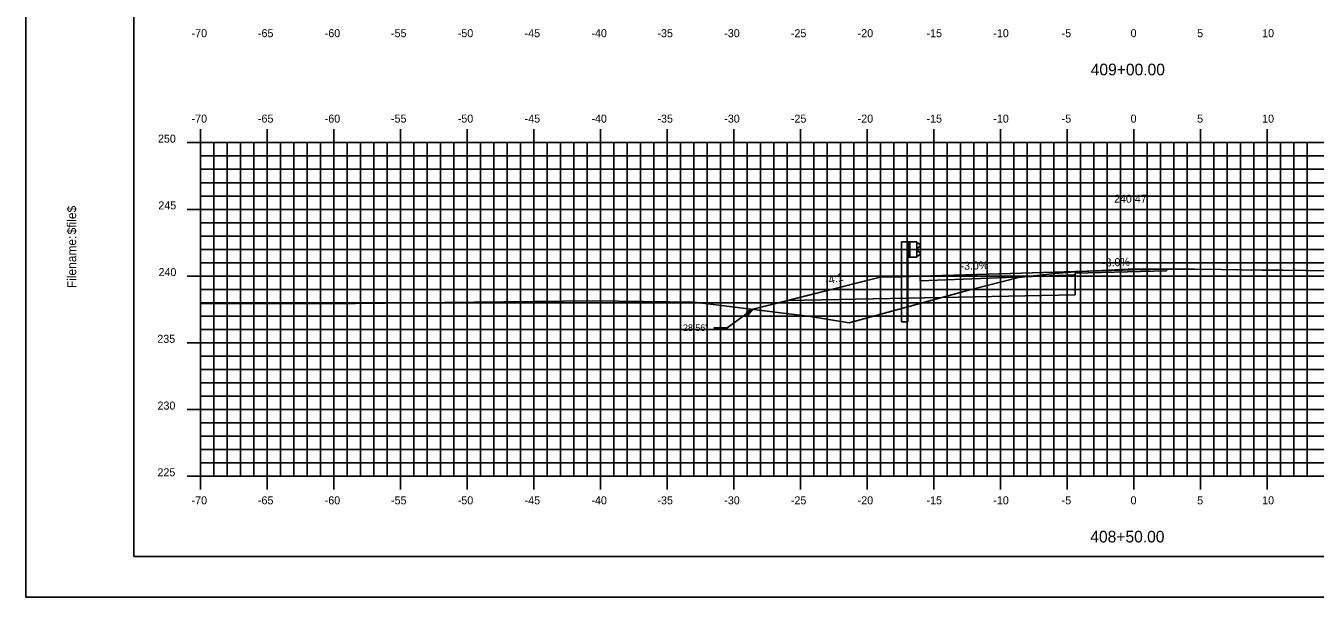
# Model space of a CAD drawing. Extents: x 1160718 to 1173142, y 616002 to 617630.
# Drawn here: x 1167440 to 1167536.7, y 616613.9 to 616656.7 of the extents above; entities that cross this region are included whole.
import ezdxf

# ---------------------------------------------------------------- set-up
doc = ezdxf.new("R2010")
doc.units = 0
for name, color, linetype in [('ANNOTATION', 7, 'Continuous'), ('BORDER', 7, 'Continuous'), ('D_Guardrail_Beam_Lt', 7, 'Continuous'), ('D_Roadway_Centerline', 7, 'Continuous'), ('D_Roadway_Centerline_Text', 7, 'Continuous'), ('D_Roadway_Edge_Shoulder', 7, 'Continuous'), ('D_Roadway_Edge_TW', 7, 'Continuous'), ('D_Roadway_Pavement', 7, 'Continuous'), ('D_Roadway_SubGrade', 7, 'Continuous'), ('H_V ANNOTATION', 7, 'Continuous'), ('MAJOR', 7, 'Continuous'), ('MINOR', 7, 'Continuous'), ('PLOT BOUNDARY', 7, 'Continuous'), ('S_Roadway_Centerline', 7, 'Continuous')]:
    doc.layers.add(name, color=color, linetype=linetype)

msp = doc.modelspace()

# ---------------------------------------------------------------- linework, layer by layer
at = {"layer": 'ANNOTATION'}
for p in [(1167494.509, 616635.442), (1167491.573, 616634.061)]:
    msp.add_line(p, (1167492.573, 616634.061), dxfattribs=at)
msp.add_lwpolyline([(1167518.683, 616636.522), (1167508.683, 616636.322), (1167497.072, 616636.089)], dxfattribs=at)
msp.add_lwpolyline([(1167494.029, 616635.253), (1167494.509, 616635.442), (1167494.174, 616635.05)], close=True, dxfattribs=at)
at = {"layer": 'BORDER'}
for p, q in [((1167448.072, 616721.928), (1167448.072, 616616.928)), ((1167448.072, 616616.928), (1167608.072, 616616.928))]:
    msp.add_line(p, q, dxfattribs=at)
at = {"layer": 'D_Guardrail_Beam_Lt'}
for p, q in [((1167505.642, 616640.505), (1167505.642, 616634.505)), ((1167506.113, 616640.505), (1167505.642, 616640.505)), ((1167506.801, 616640.505), (1167506.113, 616640.505)), ((1167506.113, 616640.505), (1167506.113, 616639.338)), ((1167506.176, 616640.505), (1167506.176, 616639.338)), ((1167506.28, 616640.505), (1167506.28, 616639.338)), ((1167506.801, 616639.338), (1167506.801, 616640.505)), ((1167506.801, 616640.422), (1167506.875, 616640.407)), ((1167506.891, 616640.4), (1167507.034, 616640.3)), ((1167506.875, 616639.436), (1167506.801, 616639.422)), ((1167506.805, 616639.957), (1167506.805, 616639.887)), ((1167507.034, 616640.157), (1167506.839, 616640.021)), ((1167506.839, 616639.822), (1167507.034, 616639.686)), ((1167507.034, 616639.543), (1167506.891, 616639.443)), ((1167506.113, 616639.338), (1167506.801, 616639.338)), ((1167506.134, 616634.505), (1167506.134, 616639.338)), ((1167506.134, 616634.505), (1167505.642, 616634.505))]:
    msp.add_line(p, q, dxfattribs=at)
for centre, major_axis, start_param, end_param in [((1167506.867, 616640.366), (0.0417, 0), 0.959931, 1.376053), ((1167506.884, 616639.957), (-0.0789, 0), 5.323254, 6.283185), ((1167506.884, 616639.887), (-0.0789, 0), 6.283185, 7.243116), ((1167506.867, 616639.477), (0.0417, 0), 4.907132, 5.323254), ((1167506.984, 616640.229), (0.0877, 0), 5.323254, 7.243116), ((1167506.984, 616639.615), (0.0877, 0), 5.323254, 7.243116)]:
    msp.add_ellipse(centre, major_axis=major_axis, ratio=0.995501, start_param=start_param, end_param=end_param, dxfattribs=at)
at = {"layer": 'D_Roadway_Centerline'}
msp.add_lwpolyline([(1167494.509, 616635.442), (1167496.76, 616636.004), (1167496.76, 616636.004), (1167504.063, 616637.856), (1167505.578, 616637.879), (1167507.063, 616637.916), (1167513.059, 616638.095), (1167518.683, 616638.265), (1167523.072, 616638.397), (1167525.526, 616638.454)], dxfattribs=at)
at = {"layer": 'D_Roadway_Edge_Shoulder'}
msp.add_lwpolyline([(1167507.063, 616637.916), (1167507.063, 616637.583)], dxfattribs=at)
at = {"layer": 'D_Roadway_Edge_TW'}
msp.add_line((1167525.526, 616638.454), (1167525.526, 616638.329), dxfattribs=at)
msp.add_lwpolyline([(1167525.526, 616638.329), (1167525.526, 616638.454), (1167523.072, 616638.397), (1167507.063, 616637.916), (1167507.063, 616637.583), (1167518.683, 616638.023), (1167518.683, 616638.14)], close=True, dxfattribs=at)
at = {"layer": 'D_Roadway_Pavement'}
msp.add_lwpolyline([(1167507.063, 616637.583), (1167507.063, 616637.583)], dxfattribs=at)
msp.add_lwpolyline([(1167507.063, 616637.583), (1167507.063, 616637.583)], dxfattribs=at)
at = {"layer": 'D_Roadway_SubGrade'}
for p, q in [((1167504.063, 616637.856), (1167494.509, 616635.442)), ((1167507.063, 616637.916), (1167504.063, 616637.856)), ((1167518.683, 616638.023), (1167507.063, 616637.583)), ((1167507.063, 616637.583), (1167507.063, 616637.916)), ((1167518.683, 616636.522), (1167518.683, 616638.023))]:
    msp.add_line(p, q, dxfattribs=at)
at = {"layer": 'MAJOR'}
for p, q in [((1167453.072, 616648.93), (1167453.072, 616647.928)), ((1167458.072, 616648.93), (1167458.072, 616647.928)), ((1167463.072, 616648.93), (1167463.072, 616647.928)), ((1167468.072, 616648.93), (1167468.072, 616647.928)), ((1167473.072, 616648.93), (1167473.072, 616647.928)), ((1167478.072, 616648.93), (1167478.072, 616647.928)), ((1167483.072, 616648.93), (1167483.072, 616647.928)), ((1167488.072, 616648.93), (1167488.072, 616647.928)), ((1167493.072, 616648.93), (1167493.072, 616647.928)), ((1167498.072, 616648.93), (1167498.072, 616647.928)), ((1167503.072, 616648.93), (1167503.072, 616647.928)), ((1167508.072, 616648.93), (1167508.072, 616647.928)), ((1167513.072, 616648.93), (1167513.072, 616647.928)), ((1167518.072, 616648.93), (1167518.072, 616647.928)), ((1167523.072, 616648.93), (1167523.072, 616647.928)), ((1167528.072, 616648.93), (1167528.072, 616647.928)), ((1167533.072, 616648.93), (1167533.072, 616647.928)), ((1167452.07, 616647.928), (1167453.072, 616647.928)), ((1167453.072, 616647.928), (1167593.072, 616647.928)), ((1167453.072, 616622.928), (1167453.072, 616647.928)), ((1167453.072, 616622.928), (1167453.072, 616647.928)), ((1167453.072, 616647.928), (1167593.072, 616647.928)), ((1167458.072, 616622.928), (1167458.072, 616647.928)), ((1167463.072, 616622.928), (1167463.072, 616647.928)), ((1167468.072, 616622.928), (1167468.072, 616647.928)), ((1167473.072, 616622.928), (1167473.072, 616647.928)), ((1167478.072, 616622.928), (1167478.072, 616647.928)), ((1167483.072, 616622.928), (1167483.072, 616647.928)), ((1167488.072, 616622.928), (1167488.072, 616647.928)), ((1167493.072, 616622.928), (1167493.072, 616647.928)), ((1167498.072, 616622.928), (1167498.072, 616647.928)), ((1167503.072, 616622.928), (1167503.072, 616647.928)), ((1167508.072, 616622.928), (1167508.072, 616647.928)), ((1167513.072, 616622.928), (1167513.072, 616647.928)), ((1167518.072, 616622.928), (1167518.072, 616647.928)), ((1167523.072, 616622.928), (1167523.072, 616647.928)), ((1167528.072, 616622.928), (1167528.072, 616647.928)), ((1167533.072, 616622.928), (1167533.072, 616647.928)), ((1167452.07, 616642.928), (1167453.072, 616642.928)), ((1167453.072, 616642.928), (1167593.072, 616642.928)), ((1167452.07, 616637.928), (1167453.072, 616637.928)), ((1167453.072, 616637.928), (1167593.072, 616637.928)), ((1167452.07, 616632.928), (1167453.072, 616632.928)), ((1167453.072, 616632.928), (1167593.072, 616632.928)), ((1167452.07, 616627.928), (1167453.072, 616627.928)), ((1167453.072, 616627.928), (1167593.072, 616627.928)), ((1167452.07, 616622.928), (1167453.072, 616622.928)), ((1167453.072, 616622.928), (1167593.072, 616622.928)), ((1167453.072, 616622.928), (1167593.072, 616622.928)), ((1167453.072, 616621.926), (1167453.072, 616622.928)), ((1167458.072, 616621.926), (1167458.072, 616622.928)), ((1167463.072, 616621.926), (1167463.072, 616622.928)), ((1167468.072, 616621.926), (1167468.072, 616622.928)), ((1167473.072, 616621.926), (1167473.072, 616622.928)), ((1167478.072, 616621.926), (1167478.072, 616622.928)), ((1167483.072, 616621.926), (1167483.072, 616622.928)), ((1167488.072, 616621.926), (1167488.072, 616622.928)), ((1167493.072, 616621.926), (1167493.072, 616622.928)), ((1167498.072, 616621.926), (1167498.072, 616622.928)), ((1167503.072, 616621.926), (1167503.072, 616622.928)), ((1167508.072, 616621.926), (1167508.072, 616622.928)), ((1167513.072, 616621.926), (1167513.072, 616622.928)), ((1167518.072, 616621.926), (1167518.072, 616622.928)), ((1167523.072, 616621.926), (1167523.072, 616622.928)), ((1167528.072, 616621.926), (1167528.072, 616622.928)), ((1167533.072, 616621.926), (1167533.072, 616622.928))]:
    msp.add_line(p, q, dxfattribs=at)
at = {"layer": 'MINOR'}
for p, q in [((1167454.072, 616622.928), (1167454.072, 616647.928)), ((1167455.072, 616622.928), (1167455.072, 616647.928)), ((1167456.072, 616622.928), (1167456.072, 616647.928)), ((1167457.072, 616622.928), (1167457.072, 616647.928)), ((1167459.072, 616622.928), (1167459.072, 616647.928)), ((1167460.072, 616622.928), (1167460.072, 616647.928)), ((1167461.072, 616622.928), (1167461.072, 616647.928)), ((1167462.072, 616622.928), (1167462.072, 616647.928)), ((1167464.072, 616622.928), (1167464.072, 616647.928)), ((1167465.072, 616622.928), (1167465.072, 616647.928)), ((1167466.072, 616622.928), (1167466.072, 616647.928)), ((1167467.072, 616622.928), (1167467.072, 616647.928)), ((1167469.072, 616622.928), (1167469.072, 616647.928)), ((1167470.072, 616622.928), (1167470.072, 616647.928)), ((1167471.072, 616622.928), (1167471.072, 616647.928)), ((1167472.072, 616622.928), (1167472.072, 616647.928)), ((1167474.072, 616622.928), (1167474.072, 616647.928)), ((1167475.072, 616622.928), (1167475.072, 616647.928)), ((1167476.072, 616622.928), (1167476.072, 616647.928)), ((1167477.072, 616622.928), (1167477.072, 616647.928)), ((1167479.072, 616622.928), (1167479.072, 616647.928)), ((1167480.072, 616622.928), (1167480.072, 616647.928)), ((1167481.072, 616622.928), (1167481.072, 616647.928)), ((1167482.072, 616622.928), (1167482.072, 616647.928)), ((1167484.072, 616622.928), (1167484.072, 616647.928)), ((1167485.072, 616622.928), (1167485.072, 616647.928)), ((1167486.072, 616622.928), (1167486.072, 616647.928)), ((1167487.072, 616622.928), (1167487.072, 616647.928)), ((1167489.072, 616622.928), (1167489.072, 616647.928)), ((1167490.072, 616622.928), (1167490.072, 616647.928)), ((1167491.072, 616622.928), (1167491.072, 616647.928)), ((1167492.072, 616622.928), (1167492.072, 616647.928)), ((1167494.072, 616622.928), (1167494.072, 616647.928)), ((1167495.072, 616622.928), (1167495.072, 616647.928)), ((1167496.072, 616622.928), (1167496.072, 616647.928)), ((1167497.072, 616622.928), (1167497.072, 616647.928)), ((1167499.072, 616622.928), (1167499.072, 616647.928)), ((1167500.072, 616622.928), (1167500.072, 616647.928)), ((1167501.072, 616622.928), (1167501.072, 616647.928)), ((1167502.072, 616622.928), (1167502.072, 616647.928)), ((1167504.072, 616622.928), (1167504.072, 616647.928)), ((1167505.072, 616622.928), (1167505.072, 616647.928)), ((1167506.072, 616622.928), (1167506.072, 616647.928)), ((1167507.072, 616622.928), (1167507.072, 616647.928)), ((1167509.072, 616622.928), (1167509.072, 616647.928)), ((1167510.072, 616622.928), (1167510.072, 616647.928)), ((1167511.072, 616622.928), (1167511.072, 616647.928)), ((1167512.072, 616622.928), (1167512.072, 616647.928)), ((1167514.072, 616622.928), (1167514.072, 616647.928)), ((1167515.072, 616622.928), (1167515.072, 616647.928)), ((1167516.072, 616622.928), (1167516.072, 616647.928)), ((1167517.072, 616622.928), (1167517.072, 616647.928)), ((1167519.072, 616622.928), (1167519.072, 616647.928)), ((1167520.072, 616622.928), (1167520.072, 616647.928)), ((1167521.072, 616622.928), (1167521.072, 616647.928)), ((1167522.072, 616622.928), (1167522.072, 616647.928)), ((1167524.072, 616622.928), (1167524.072, 616647.928)), ((1167525.072, 616622.928), (1167525.072, 616647.928)), ((1167526.072, 616622.928), (1167526.072, 616647.928)), ((1167527.072, 616622.928), (1167527.072, 616647.928)), ((1167529.072, 616622.928), (1167529.072, 616647.928)), ((1167530.072, 616622.928), (1167530.072, 616647.928)), ((1167531.072, 616622.928), (1167531.072, 616647.928)), ((1167532.072, 616622.928), (1167532.072, 616647.928)), ((1167534.072, 616622.928), (1167534.072, 616647.928)), ((1167535.072, 616622.928), (1167535.072, 616647.928)), ((1167536.072, 616622.928), (1167536.072, 616647.928)), ((1167453.072, 616646.928), (1167593.072, 616646.928)), ((1167453.072, 616646.928), (1167454.074, 616646.928)), ((1167453.072, 616645.928), (1167593.072, 616645.928)), ((1167453.072, 616645.928), (1167454.074, 616645.928)), ((1167453.072, 616644.928), (1167593.072, 616644.928)), ((1167453.072, 616644.928), (1167454.074, 616644.928)), ((1167453.072, 616643.928), (1167593.072, 616643.928)), ((1167453.072, 616643.928), (1167454.074, 616643.928)), ((1167453.072, 616641.928), (1167593.072, 616641.928)), ((1167453.072, 616641.928), (1167454.074, 616641.928)), ((1167453.072, 616640.928), (1167593.072, 616640.928)), ((1167453.072, 616640.928), (1167454.074, 616640.928)), ((1167453.072, 616639.928), (1167593.072, 616639.928)), ((1167453.072, 616639.928), (1167454.074, 616639.928)), ((1167453.072, 616638.928), (1167593.072, 616638.928)), ((1167453.072, 616638.928), (1167454.074, 616638.928)), ((1167453.072, 616636.928), (1167593.072, 616636.928)), ((1167453.072, 616636.928), (1167454.074, 616636.928)), ((1167453.072, 616635.928), (1167593.072, 616635.928)), ((1167453.072, 616635.928), (1167454.074, 616635.928)), ((1167453.072, 616634.928), (1167593.072, 616634.928)), ((1167453.072, 616634.928), (1167454.074, 616634.928)), ((1167453.072, 616633.928), (1167593.072, 616633.928)), ((1167453.072, 616633.928), (1167454.074, 616633.928)), ((1167453.072, 616631.928), (1167593.072, 616631.928)), ((1167453.072, 616631.928), (1167454.074, 616631.928)), ((1167453.072, 616630.928), (1167593.072, 616630.928)), ((1167453.072, 616630.928), (1167454.074, 616630.928)), ((1167453.072, 616629.928), (1167593.072, 616629.928)), ((1167453.072, 616629.928), (1167454.074, 616629.928)), ((1167453.072, 616628.928), (1167593.072, 616628.928)), ((1167453.072, 616628.928), (1167454.074, 616628.928)), ((1167453.072, 616626.928), (1167593.072, 616626.928)), ((1167453.072, 616626.928), (1167454.074, 616626.928)), ((1167453.072, 616625.928), (1167593.072, 616625.928)), ((1167453.072, 616625.928), (1167454.074, 616625.928)), ((1167453.072, 616624.928), (1167593.072, 616624.928)), ((1167453.072, 616624.928), (1167454.074, 616624.928)), ((1167453.072, 616623.928), (1167593.072, 616623.928)), ((1167453.072, 616623.928), (1167454.074, 616623.928))]:
    msp.add_line(p, q, dxfattribs=at)
at = {"layer": 'PLOT BOUNDARY'}
msp.add_lwpolyline([(1167439.979, 616613.869), (1167609.979, 616613.869), (1167609.979, 616723.869), (1167439.979, 616723.869)], close=True, dxfattribs=at)
at = {"layer": 'S_Roadway_Centerline'}
msp.add_lwpolyline([(1167453.072, 616635.858), (1167464.693, 616635.867), (1167482.5, 616636.07), (1167490.124, 616635.986), (1167498.813, 616634.907), (1167501.737, 616634.418), (1167510.604, 616636.848), (1167514.43, 616637.827), (1167517.16, 616638.115), (1167518.683, 616638.254), (1167520.179, 616638.332), (1167522.638, 616638.46), (1167525.225, 616638.454), (1167527.662, 616638.449), (1167529.661, 616638.424), (1167532.687, 616638.385), (1167534.231, 616638.363), (1167537.712, 616638.314)], dxfattribs=at)

# ---------------------------------------------------------------- texts
at = {"layer": 'ANNOTATION'}
for s, rotation, p in [('-3.0%', 1.71836, (1167510.081, 616638.391)), ('-3.0%', 1.71836, (1167520.695, 616638.64)), ('-4:1', 14.03624, (1167499.995, 616637.27))]:
    msp.add_text(s, height=0.6, rotation=rotation, dxfattribs=at).set_placement(p)
msp.add_text("28.56'", height=0.5, dxfattribs=at).set_placement((1167489.264, 616633.811))
at = {"layer": 'BORDER'}
for s, p in [('$file$', (1167443.757, 616641.054)), ('Filename:', (1167443.757, 616637.027))]:
    msp.add_text(s, height=0.6696, rotation=90, dxfattribs=at).set_placement(p)
at = {"layer": 'D_Roadway_Centerline'}
for s, p in [('C', (1167523.067, 616638.397)), ('L', (1167523.072, 616638.389))]:
    msp.add_text(s, height=0.0146, dxfattribs=at).set_placement(p)
at = {"layer": 'D_Roadway_Centerline_Text'}
msp.add_text('240.47', height=0.6, dxfattribs=at).set_placement((1167521.59, 616643.429))
at = {"layer": 'H_V ANNOTATION'}
for s, height, p in [('-70', 0.6, (1167452.414, 616655.828)), ('-65', 0.6, (1167457.39, 616655.828)), ('-60', 0.6, (1167462.398, 616655.828)), ('-55', 0.6, (1167467.368, 616655.828)), ('-50', 0.6, (1167472.376, 616655.828)), ('-45', 0.6, (1167477.39, 616655.828)), ('-40', 0.6, (1167482.398, 616655.828)), ('-35', 0.6, (1167487.352, 616655.828)), ('-30', 0.6, (1167492.36, 616655.828)), ('-25', 0.6, (1167497.357, 616655.828)), ('-20', 0.6, (1167502.365, 616655.828)), ('-15', 0.6, (1167507.529, 616655.828)), ('-10', 0.6, (1167512.537, 616655.828)), ('-5', 0.6, (1167517.663, 616655.828)), ('0', 0.6, (1167522.831, 616655.828)), ('5', 0.6, (1167527.823, 616655.828)), ('10', 0.6, (1167532.697, 616655.828)), ('409+00.00', 0.875, (1167519.842, 616652.971)), ('-70', 0.6, (1167452.414, 616649.428)), ('-65', 0.6, (1167457.39, 616649.428)), ('-60', 0.6, (1167462.398, 616649.428)), ('-55', 0.6, (1167467.368, 616649.428)), ('-50', 0.6, (1167472.376, 616649.428)), ('-45', 0.6, (1167477.39, 616649.428)), ('-40', 0.6, (1167482.398, 616649.428)), ('-35', 0.6, (1167487.352, 616649.428)), ('-30', 0.6, (1167492.36, 616649.428)), ('-25', 0.6, (1167497.357, 616649.428)), ('-20', 0.6, (1167502.365, 616649.428)), ('-15', 0.6, (1167507.529, 616649.428)), ('-10', 0.6, (1167512.537, 616649.428)), ('-5', 0.6, (1167517.663, 616649.428)), ('0', 0.6, (1167522.831, 616649.428)), ('5', 0.6, (1167527.823, 616649.428)), ('10', 0.6, (1167532.697, 616649.428)), ('250', 0.6, (1167449.891, 616647.928)), ('245', 0.6, (1167449.918, 616642.928)), ('240', 0.6, (1167449.934, 616637.928)), ('235', 0.6, (1167449.843, 616632.928)), ('230', 0.6, (1167449.859, 616627.928)), ('225', 0.6, (1167449.854, 616622.928)), ('-70', 0.6, (1167452.414, 616620.828)), ('-65', 0.6, (1167457.39, 616620.828)), ('-60', 0.6, (1167462.398, 616620.828)), ('-55', 0.6, (1167467.368, 616620.828)), ('-50', 0.6, (1167472.376, 616620.828)), ('-45', 0.6, (1167477.39, 616620.828)), ('-40', 0.6, (1167482.398, 616620.828)), ('-35', 0.6, (1167487.352, 616620.828)), ('-30', 0.6, (1167492.36, 616620.828)), ('-25', 0.6, (1167497.357, 616620.828)), ('-20', 0.6, (1167502.365, 616620.828)), ('-15', 0.6, (1167507.529, 616620.828)), ('-10', 0.6, (1167512.537, 616620.828)), ('-5', 0.6, (1167517.663, 616620.828)), ('0', 0.6, (1167522.831, 616620.828)), ('5', 0.6, (1167527.823, 616620.828)), ('10', 0.6, (1167532.697, 616620.828)), ('408+50.00', 0.875, (1167519.81, 616617.971))]:
    msp.add_text(s, height=height, dxfattribs=at).set_placement(p)

doc.saveas('drawing.dxf')
